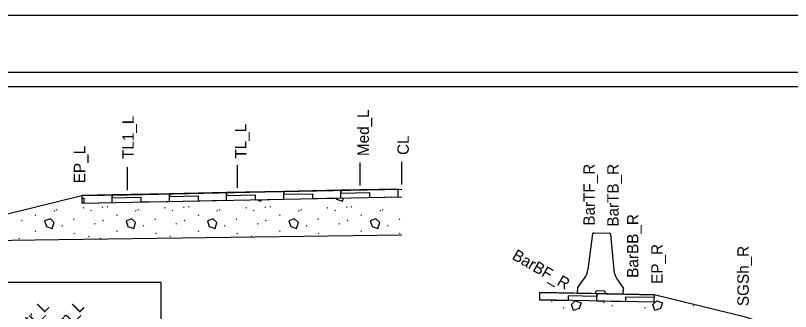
# Model space of a CAD drawing. Extents: x 0 to 1.42, y 0 to 0.92.
# Drawn here: x 0.309 to 0.874, y 0.701 to 0.917 of the extents above; entities that cross this region are included whole.
import ezdxf

# ---------------------------------------------------------------- set-up
doc = ezdxf.new("R2010")
doc.units = 0
for name, color, linetype in [('#plot_shape', 7, 'Continuous'), ('Level 14', 7, 'Continuous'), ('Level 63', 7, 'Continuous'), ('P_ODOT_PLAN_Border', 7, 'Continuous'), ('P_RDWY_PLAN_Detail', 7, 'Continuous'), ('P_RDWY_PLAN_DetailTx', 7, 'Continuous')]:
    doc.layers.add(name, color=color, linetype=linetype)

msp = doc.modelspace()

# ---------------------------------------------------------------- linework, layer by layer
at = {"layer": '#plot_shape'}
for points in [[(0, 0), (1.416666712, 0), (1.416666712, 0.916666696), (0, 0.916666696)], [(1.9999941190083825e-09, 1.3333161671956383e-09), (1.416666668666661, 1.3333161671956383e-09), (1.416666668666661, 0.916666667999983), (1.9999941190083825e-09, 0.916666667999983)]]:
    msp.add_lwpolyline(points, close=True, dxfattribs=at)
at = {"layer": 'Level 14'}
for p, q in [((0.7300565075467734, 0.7573254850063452), (0.7266381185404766, 0.7313387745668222)), ((0.730942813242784, 0.7581609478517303), (0.7423305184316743, 0.757933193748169)), ((0.7431772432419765, 0.7570630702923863), (0.7455538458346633, 0.7309604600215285)), ((0.7191560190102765, 0.7181983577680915), (0.7241561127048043, 0.7250988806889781)), ((0.7477898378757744, 0.7246262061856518), (0.7525045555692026, 0.7175313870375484)), ((0.7190740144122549, 0.71409812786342), (0.7191560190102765, 0.7181983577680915)), ((0.7524225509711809, 0.7134311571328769), (0.7525045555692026, 0.7175313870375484)), ((0.7190740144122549, 0.71409812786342), (0.7319214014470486, 0.7138411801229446)), ((0.7319214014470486, 0.7138411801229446), (0.7327851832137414, 0.7160115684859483)), ((0.7327851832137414, 0.7160115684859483), (0.7387988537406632, 0.7158912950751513)), ((0.7395751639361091, 0.7136881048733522), (0.7387988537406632, 0.7158912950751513)), ((0.7395751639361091, 0.7136881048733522), (0.7524225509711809, 0.7134311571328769))]:
    msp.add_line(p, q, dxfattribs=at)
for centre, start, end in [((0.7130856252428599, 0.7331225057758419), 324.0626538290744, 352.5107954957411), ((0.759168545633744, 0.7321988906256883), 185.20257327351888, 213.62627327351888)]:
    msp.add_arc(centre, 0.01367016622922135, start, end, dxfattribs=at)
for centre, major_axis, ratio, start_param, end_param in [((0.7308618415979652, 0.7572851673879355), (1.7651646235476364e-05, 0.0008825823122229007), 0.9122254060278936, 6.2052310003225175, 7.824384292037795), ((0.7423937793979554, 0.7570795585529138), (1.7194650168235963e-05, 0.000859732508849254), 0.9122254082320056, 4.71366656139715, 6.389459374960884)]:
    msp.add_ellipse(centre, major_axis=major_axis, ratio=ratio, start_param=start_param, end_param=end_param, dxfattribs=at)
at = {"layer": 'Level 63'}
for points in [[(0.9149281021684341, 0.24947988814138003), (0.07444556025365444, 0.24947988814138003), (0.07444556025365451, 0.8648110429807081), (0.9149281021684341, 0.8648110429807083)], [(0.41534290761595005, 0.6217266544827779), (0.2093492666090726, 0.6217266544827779), (0.2093492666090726, 0.7221789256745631), (0.41534290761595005, 0.7221789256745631)]]:
    msp.add_lwpolyline(points, close=True, dxfattribs=at)
at = {"layer": 'P_ODOT_PLAN_Border'}
for p, q in [((1.3087924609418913, 0.8750000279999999), (0.06250000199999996, 0.8750000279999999)), ((1.3087924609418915, 0.8750000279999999), (0.06250000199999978, 0.8750000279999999)), ((1.3087924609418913, 0.8750000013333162), (0.06250000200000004, 0.8750000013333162)), ((1.3087924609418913, 0.8750000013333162), (0.06250000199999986, 0.8750000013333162))]:
    msp.add_line(p, q, dxfattribs=at)
for points in [[(0.06250000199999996, 0.041666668), (1.395833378, 0.041666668), (1.395833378, 0.8750000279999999), (0.06250000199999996, 0.8750000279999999)], [(0.06250000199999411, 0.04166666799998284), (1.3958333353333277, 0.04166666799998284), (1.3958333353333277, 0.8750000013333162), (0.06250000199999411, 0.8750000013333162)]]:
    msp.add_lwpolyline(points, close=True, dxfattribs=at)
at = {"layer": 'P_RDWY_PLAN_Detail'}
for p, q in [((0.3558127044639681, 0.7848315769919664), (0.3558831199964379, 0.7847611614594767)), ((0.5838676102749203, 0.7843138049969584), (0.5835406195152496, 0.7839868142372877)), ((0.5836819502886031, 0.7843100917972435), (0.584005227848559, 0.7839868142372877)), ((0.3380731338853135, 0.7743840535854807), (0.33760852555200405, 0.7739194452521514)), ((0.33760852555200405, 0.7743840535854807), (0.3380731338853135, 0.7739194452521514)), ((0.3397766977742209, 0.7751592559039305), (0.3393120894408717, 0.774694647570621)), ((0.3393120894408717, 0.7751592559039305), (0.3397766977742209, 0.774694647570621)), ((0.35913476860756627, 0.7767079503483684), (0.3586707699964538, 0.776243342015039)), ((0.3586707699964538, 0.7767079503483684), (0.35913476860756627, 0.776243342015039)), ((0.36471006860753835, 0.7746937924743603), (0.364245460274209, 0.7742291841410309)), ((0.364245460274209, 0.7746937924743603), (0.36471006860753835, 0.7742291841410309)), ((0.37307301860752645, 0.7770176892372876), (0.37260841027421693, 0.7765530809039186)), ((0.37260841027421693, 0.7770176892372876), (0.37307301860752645, 0.7765530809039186)), ((0.3766354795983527, 0.7773274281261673), (0.37617087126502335, 0.7768628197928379)), ((0.37617087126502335, 0.7773274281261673), (0.3766354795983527, 0.7768628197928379)), ((0.3973879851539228, 0.7743840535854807), (0.3969233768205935, 0.7739194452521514)), ((0.3969233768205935, 0.7743840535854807), (0.3973879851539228, 0.7739194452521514)), ((0.39909154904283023, 0.7751592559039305), (0.39862694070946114, 0.774694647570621)), ((0.39862694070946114, 0.7751592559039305), (0.39909154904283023, 0.774694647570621)), ((0.41844961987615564, 0.7767079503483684), (0.41798562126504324, 0.776243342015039)), ((0.41798562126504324, 0.7767079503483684), (0.41844961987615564, 0.776243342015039)), ((0.42402491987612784, 0.7746937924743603), (0.42356031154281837, 0.7742291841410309)), ((0.42356031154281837, 0.7746937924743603), (0.42402491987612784, 0.7742291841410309)), ((0.43238786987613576, 0.7770176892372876), (0.43192326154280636, 0.7765530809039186)), ((0.43192326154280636, 0.7770176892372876), (0.43238786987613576, 0.7765530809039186)), ((0.43595033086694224, 0.7773274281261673), (0.43548572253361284, 0.7768628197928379)), ((0.43548572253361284, 0.7773274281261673), (0.43595033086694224, 0.7768628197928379)), ((0.45670283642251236, 0.7743840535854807), (0.45623822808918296, 0.7739194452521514)), ((0.45623822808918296, 0.7743840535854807), (0.45670283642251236, 0.7739194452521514)), ((0.45840640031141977, 0.7751592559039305), (0.4579417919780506, 0.774694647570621)), ((0.4579417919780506, 0.7751592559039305), (0.45840640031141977, 0.774694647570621)), ((0.47776447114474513, 0.7767079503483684), (0.4773004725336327, 0.776243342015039)), ((0.4773004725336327, 0.7767079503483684), (0.47776447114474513, 0.776243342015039)), ((0.4833397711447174, 0.7746937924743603), (0.4828751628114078, 0.7742291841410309)), ((0.4828751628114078, 0.7746937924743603), (0.4833397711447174, 0.7742291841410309)), ((0.4917027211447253, 0.7770176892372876), (0.4912381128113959, 0.7765530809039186)), ((0.4912381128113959, 0.7770176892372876), (0.4917027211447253, 0.7765530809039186)), ((0.4952651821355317, 0.7773274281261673), (0.4948005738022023, 0.7768628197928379)), ((0.4948005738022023, 0.7773274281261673), (0.4952651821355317, 0.7768628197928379)), ((0.5160176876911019, 0.7743840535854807), (0.5155530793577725, 0.7739194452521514)), ((0.5155530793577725, 0.7743840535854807), (0.5160176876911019, 0.7739194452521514)), ((0.5177212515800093, 0.7751592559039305), (0.5172566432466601, 0.774694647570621)), ((0.5172566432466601, 0.7751592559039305), (0.5177212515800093, 0.774694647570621)), ((0.5370793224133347, 0.7767079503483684), (0.5366153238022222, 0.776243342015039)), ((0.5366153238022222, 0.7767079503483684), (0.5370793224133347, 0.776243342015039)), ((0.5426546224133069, 0.7746937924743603), (0.5421900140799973, 0.7742291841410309)), ((0.5421900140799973, 0.7746937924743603), (0.5426546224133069, 0.7742291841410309)), ((0.5510175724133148, 0.7770176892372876), (0.5505529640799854, 0.7765530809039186)), ((0.5505529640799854, 0.7770176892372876), (0.5510175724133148, 0.7765530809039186)), ((0.5545800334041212, 0.7773274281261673), (0.5541154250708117, 0.7768628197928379)), ((0.5541154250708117, 0.7773274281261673), (0.5545800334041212, 0.7768628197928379)), ((0.5753325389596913, 0.7743840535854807), (0.574867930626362, 0.7739194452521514)), ((0.574867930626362, 0.7743840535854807), (0.5753325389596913, 0.7739194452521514)), ((0.5770361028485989, 0.7751592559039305), (0.5765714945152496, 0.774694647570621)), ((0.5765714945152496, 0.7751592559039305), (0.5770361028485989, 0.774694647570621)), ((0.3242897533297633, 0.7712866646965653), (0.3238251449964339, 0.7708220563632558)), ((0.3238251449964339, 0.7712866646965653), (0.3242897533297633, 0.7708220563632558)), ((0.3521662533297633, 0.7683441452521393), (0.3517016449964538, 0.7678795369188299)), ((0.3517016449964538, 0.7683441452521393), (0.3521662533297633, 0.7678795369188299)), ((0.3836046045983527, 0.7712866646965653), (0.3831399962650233, 0.7708220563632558)), ((0.3831399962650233, 0.7712866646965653), (0.3836046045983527, 0.7708220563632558)), ((0.41148110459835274, 0.7683441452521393), (0.4110164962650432, 0.7678795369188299)), ((0.4110164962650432, 0.7683441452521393), (0.41148110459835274, 0.7678795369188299)), ((0.4429194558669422, 0.7712866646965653), (0.4424548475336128, 0.7708220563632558)), ((0.4424548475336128, 0.7712866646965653), (0.4429194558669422, 0.7708220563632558)), ((0.47079595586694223, 0.7683441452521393), (0.47033134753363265, 0.7678795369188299)), ((0.47033134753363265, 0.7683441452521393), (0.47079595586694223, 0.7678795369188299)), ((0.5022343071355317, 0.7712866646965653), (0.5017696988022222, 0.7708220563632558)), ((0.5017696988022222, 0.7712866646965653), (0.5022343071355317, 0.7708220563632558)), ((0.5301108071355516, 0.7683441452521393), (0.5296461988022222, 0.7678795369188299)), ((0.5296461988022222, 0.7683441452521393), (0.5301108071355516, 0.7678795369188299)), ((0.5615491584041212, 0.7712866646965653), (0.5610845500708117, 0.7708220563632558)), ((0.5610845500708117, 0.7712866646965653), (0.5615491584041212, 0.7708220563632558)), ((0.5894256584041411, 0.7683441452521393), (0.5889610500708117, 0.7678795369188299)), ((0.5889610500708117, 0.7683441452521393), (0.5894256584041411, 0.7678795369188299)), ((0.31422323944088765, 0.7674149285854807), (0.31375863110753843, 0.7669503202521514)), ((0.31375863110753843, 0.7674149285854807), (0.31422323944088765, 0.7669503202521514)), ((0.34364843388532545, 0.7635431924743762), (0.34318382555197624, 0.763078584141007)), ((0.34318382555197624, 0.7635431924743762), (0.34364843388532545, 0.763078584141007)), ((0.36749771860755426, 0.7649370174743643), (0.36703311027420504, 0.7644724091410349)), ((0.36703311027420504, 0.7649370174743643), (0.36749771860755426, 0.7644724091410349)), ((0.3735380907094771, 0.7674149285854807), (0.37307348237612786, 0.7669503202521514)), ((0.37307348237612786, 0.7674149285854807), (0.3735380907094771, 0.7669503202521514)), ((0.4029632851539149, 0.7635431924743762), (0.40249867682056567, 0.763078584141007)), ((0.40249867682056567, 0.7635431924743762), (0.4029632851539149, 0.763078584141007)), ((0.42681256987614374, 0.7649370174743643), (0.4263479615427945, 0.7644724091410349)), ((0.4263479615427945, 0.7649370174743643), (0.42681256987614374, 0.7644724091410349)), ((0.43285294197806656, 0.7674149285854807), (0.4323883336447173, 0.7669503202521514)), ((0.4323883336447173, 0.7674149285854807), (0.43285294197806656, 0.7669503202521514)), ((0.4622781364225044, 0.7635431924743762), (0.4618135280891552, 0.763078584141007)), ((0.4618135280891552, 0.7635431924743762), (0.4622781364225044, 0.763078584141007)), ((0.48612742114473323, 0.7649370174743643), (0.485662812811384, 0.7644724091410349)), ((0.485662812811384, 0.7649370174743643), (0.48612742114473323, 0.7644724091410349)), ((0.49216779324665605, 0.7674149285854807), (0.49170318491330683, 0.7669503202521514)), ((0.49170318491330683, 0.7674149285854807), (0.49216779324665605, 0.7669503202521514)), ((0.5215929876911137, 0.7635431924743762), (0.5211283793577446, 0.763078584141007)), ((0.5211283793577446, 0.7635431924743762), (0.5215929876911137, 0.763078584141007)), ((0.5454422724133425, 0.7649370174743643), (0.5449776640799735, 0.7644724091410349)), ((0.5449776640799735, 0.7649370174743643), (0.5454422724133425, 0.7644724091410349)), ((0.5514826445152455, 0.7674149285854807), (0.5510180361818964, 0.7669503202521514)), ((0.5510180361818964, 0.7674149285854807), (0.5514826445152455, 0.7669503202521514)), ((0.5809078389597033, 0.7635431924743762), (0.5804432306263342, 0.763078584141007)), ((0.5804432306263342, 0.7635431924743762), (0.5809078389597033, 0.763078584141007)), ((0.3242897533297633, 0.7596714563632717), (0.3238251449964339, 0.7592068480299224)), ((0.3238251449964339, 0.7596714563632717), (0.3242897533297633, 0.7592068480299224)), ((0.3524759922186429, 0.7579678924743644), (0.35201138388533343, 0.757503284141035)), ((0.35201138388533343, 0.7579678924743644), (0.3524759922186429, 0.757503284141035)), ((0.3836046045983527, 0.7596714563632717), (0.3831399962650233, 0.7592068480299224)), ((0.3831399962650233, 0.7596714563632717), (0.3836046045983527, 0.7592068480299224)), ((0.41179084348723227, 0.7579678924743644), (0.4113262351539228, 0.757503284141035)), ((0.4113262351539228, 0.7579678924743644), (0.41179084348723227, 0.757503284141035)), ((0.4429194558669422, 0.7596714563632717), (0.4424548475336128, 0.7592068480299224)), ((0.4424548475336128, 0.7596714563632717), (0.4429194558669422, 0.7592068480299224)), ((0.4711056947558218, 0.7579678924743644), (0.47064108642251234, 0.757503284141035)), ((0.47064108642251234, 0.7579678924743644), (0.4711056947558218, 0.757503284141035)), ((0.5022343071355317, 0.7596714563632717), (0.5017696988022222, 0.7592068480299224)), ((0.5017696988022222, 0.7596714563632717), (0.5022343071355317, 0.7592068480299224)), ((0.5304205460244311, 0.7579678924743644), (0.5299559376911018, 0.757503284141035)), ((0.5299559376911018, 0.7579678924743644), (0.5304205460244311, 0.757503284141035)), ((0.5615491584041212, 0.7596714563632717), (0.5610845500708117, 0.7592068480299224)), ((0.5610845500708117, 0.7596714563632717), (0.5615491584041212, 0.7592068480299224)), ((0.5897353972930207, 0.7579678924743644), (0.5892707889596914, 0.757503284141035)), ((0.5892707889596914, 0.7579678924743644), (0.5897353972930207, 0.757503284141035)), ((0.312209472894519, 0.7542510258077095), (0.31174486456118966, 0.7537864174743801)), ((0.31174486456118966, 0.7542510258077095), (0.312209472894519, 0.7537864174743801)), ((0.36300650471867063, 0.7557997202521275), (0.36254189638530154, 0.755335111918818)), ((0.36254189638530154, 0.7557997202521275), (0.36300650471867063, 0.755335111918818)), ((0.37152432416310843, 0.7542510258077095), (0.3710597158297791, 0.7537864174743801)), ((0.3710597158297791, 0.7542510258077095), (0.37152432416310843, 0.7537864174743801)), ((0.4223213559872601, 0.7557997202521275), (0.4218567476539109, 0.755335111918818)), ((0.4218567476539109, 0.7557997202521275), (0.4223213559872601, 0.755335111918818)), ((0.4816362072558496, 0.7557997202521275), (0.4811715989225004, 0.755335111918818)), ((0.4811715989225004, 0.7557997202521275), (0.4816362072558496, 0.755335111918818)), ((0.7000815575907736, 0.7085692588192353), (0.700546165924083, 0.7081046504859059)), ((0.700546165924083, 0.7085692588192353), (0.7000815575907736, 0.7081046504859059)), ((0.7380245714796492, 0.7076400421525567), (0.7384891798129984, 0.7071754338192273)), ((0.7384891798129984, 0.7076400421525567), (0.7380245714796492, 0.7071754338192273)), ((0.7975714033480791, 0.707407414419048), (0.7973394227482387, 0.7071754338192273)), ((0.7975722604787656, 0.7074072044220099), (0.7978040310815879, 0.7071754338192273)), ((0.7085993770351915, 0.7037683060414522), (0.7090639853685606, 0.703303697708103)), ((0.7090639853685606, 0.7037683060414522), (0.7085993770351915, 0.703303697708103)), ((0.744064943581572, 0.7051621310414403), (0.7445295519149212, 0.7046975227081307)), ((0.7445295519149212, 0.7051621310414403), (0.744064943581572, 0.7046975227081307)), ((0.7679142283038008, 0.7037683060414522), (0.76837883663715, 0.703303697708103)), ((0.76837883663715, 0.7037683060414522), (0.7679142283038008, 0.703303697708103)), ((0.8033797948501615, 0.7051621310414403), (0.8038444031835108, 0.7046975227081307)), ((0.8038444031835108, 0.7051621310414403), (0.8033797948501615, 0.7046975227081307))]:
    msp.add_line(p, q, dxfattribs=at)
for points in [[(0.13057917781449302, 0.7575004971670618), (0.187180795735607, 0.7433500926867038), (0.2205141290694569, 0.7516834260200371), (0.3576843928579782, 0.7852901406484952), (0.3910177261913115, 0.7859568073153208), (0.49101772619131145, 0.7879568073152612), (0.5910177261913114, 0.7899568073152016)], [(0.3576843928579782, 0.7852901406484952), (0.3577943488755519, 0.7797923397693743), (0.5910177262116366, 0.7844568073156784)], [(0.4289329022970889, 0.781215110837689), (0.4289807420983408, 0.7811991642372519), (0.4289864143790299, 0.7812161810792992)], [(0.48489030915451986, 0.782334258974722), (0.4882955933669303, 0.7811991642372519), (0.4886993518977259, 0.782410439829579)], [(0.5431269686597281, 0.783498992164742), (0.5434289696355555, 0.7825929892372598), (0.5476104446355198, 0.7811991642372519), (0.548412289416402, 0.7836046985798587)], [(0.22051412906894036, 0.7516834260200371), (0.34101772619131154, 0.7532901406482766), (0.5910177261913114, 0.7566234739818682)], [(0.8810170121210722, 0.6834707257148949), (0.8414791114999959, 0.6966500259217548), (0.7748124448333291, 0.712983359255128), (0.7414791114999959, 0.7136500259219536), (0.6914791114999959, 0.714650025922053)], [(0.7748124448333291, 0.712983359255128), (0.7747024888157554, 0.7074855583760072), (0.6914791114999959, 0.7091500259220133)], [(0.7174696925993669, 0.7085550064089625), (0.7216084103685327, 0.7071754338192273), (0.7202145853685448, 0.7029939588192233), (0.7160331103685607, 0.7016001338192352), (0.7146392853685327, 0.7057816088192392), (0.7174137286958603, 0.7085560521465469)]]:
    msp.add_lwpolyline(points, dxfattribs=at)
for points in [[(0.3799498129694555, 0.7858448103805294), (0.3576843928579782, 0.7852901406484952), (0.3577238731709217, 0.7833161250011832), (0.3591164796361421, 0.7833439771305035), (0.3591164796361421, 0.7798187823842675), (0.3799498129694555, 0.7802354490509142)], [(0.42161647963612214, 0.7866781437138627), (0.3799498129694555, 0.7858448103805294), (0.3799498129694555, 0.7837606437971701), (0.4007831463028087, 0.7841773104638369), (0.4007831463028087, 0.7806521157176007), (0.42161647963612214, 0.7810687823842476)], [(0.46328314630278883, 0.7875114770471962), (0.42161647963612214, 0.7866781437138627), (0.42161647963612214, 0.7845939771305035), (0.4424498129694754, 0.7850106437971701), (0.4424498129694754, 0.7814854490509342), (0.46328314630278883, 0.781902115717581)], [(0.5049498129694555, 0.7883448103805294), (0.46328314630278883, 0.7875114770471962), (0.46328314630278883, 0.7854273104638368), (0.48411647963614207, 0.7858439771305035), (0.48411647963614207, 0.7823187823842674), (0.5049498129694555, 0.7827354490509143)], [(0.5466164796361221, 0.7891781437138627), (0.5049498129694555, 0.7883448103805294), (0.5049498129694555, 0.7862606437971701), (0.5257831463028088, 0.7866773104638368), (0.5257831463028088, 0.7831521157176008), (0.5466164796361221, 0.7835687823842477)], [(0.5882831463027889, 0.7900114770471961), (0.5466164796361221, 0.7891781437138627), (0.5466164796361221, 0.7870939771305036), (0.5674498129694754, 0.7875106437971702), (0.5674498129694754, 0.7839854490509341), (0.5882831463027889, 0.7844021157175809)], [(0.3362147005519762, 0.7613750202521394), (0.33760852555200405, 0.7655564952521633), (0.33482087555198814, 0.7683441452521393), (0.330639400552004, 0.7669503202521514), (0.3320332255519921, 0.7627688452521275)], [(0.39552955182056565, 0.7613750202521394), (0.3969233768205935, 0.7655564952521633), (0.39413572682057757, 0.7683441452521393), (0.38995425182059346, 0.7669503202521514), (0.39134807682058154, 0.7627688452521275)], [(0.45484440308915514, 0.7613750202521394), (0.45623822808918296, 0.7655564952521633), (0.4534505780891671, 0.7683441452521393), (0.449269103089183, 0.7669503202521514), (0.4506629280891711, 0.7627688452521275)], [(0.5141592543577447, 0.7613750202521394), (0.5155530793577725, 0.7655564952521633), (0.5127654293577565, 0.7683441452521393), (0.5085839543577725, 0.7669503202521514), (0.5099777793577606, 0.7627688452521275)], [(0.5734741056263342, 0.7613750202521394), (0.574867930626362, 0.7655564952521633), (0.5720802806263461, 0.7683441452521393), (0.567898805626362, 0.7669503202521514), (0.5692926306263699, 0.7627688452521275)], [(0.6914791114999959, 0.7146500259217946), (0.7331457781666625, 0.7138166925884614), (0.7331457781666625, 0.7117325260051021), (0.7123124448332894, 0.7121491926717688), (0.7123124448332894, 0.7086239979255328), (0.6914791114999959, 0.7090406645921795)], [(0.7331457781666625, 0.7138166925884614), (0.7748124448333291, 0.712983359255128), (0.7748124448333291, 0.7108991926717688), (0.7539791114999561, 0.7113158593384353), (0.7539791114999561, 0.7077906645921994), (0.7331457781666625, 0.7082073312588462)], [(0.7753479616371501, 0.7016001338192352), (0.7739541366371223, 0.7057816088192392), (0.7767417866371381, 0.7085692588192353), (0.7809232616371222, 0.7071754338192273), (0.7795294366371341, 0.7029939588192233)]]:
    msp.add_lwpolyline(points, close=True, dxfattribs=at)
at = {"layer": 'P_RDWY_PLAN_DetailTx'}
for p, q in [((0.5605075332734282, 0.7926799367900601), (0.5605075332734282, 0.8093466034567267)), ((0.5910177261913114, 0.793290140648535), (0.5910177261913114, 0.8099568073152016)), ((0.3910177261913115, 0.7892901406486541), (0.3910177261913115, 0.8059568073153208)), ((0.4711910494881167, 0.7908936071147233), (0.4711910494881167, 0.8075602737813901))]:
    msp.add_line(p, q, dxfattribs=at)

# ---------------------------------------------------------------- texts
for s, height, rotation, p in [('Med_L', 0.008330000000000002, 90.00000153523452, (0.5669841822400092, 0.8141318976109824)), ('TL1_L', 0.008330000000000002, 90.00000153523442, (0.3956222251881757, 0.8120038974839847)), ('TL_L', 0.008330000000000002, 90.0000015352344, (0.4776676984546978, 0.812345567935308)), ('CL', 0.008330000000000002, 90.00000153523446, (0.59604460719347, 0.8149567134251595)), ('EP_L', 0.008330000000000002, 90.00000153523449, (0.3601884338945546, 0.7942870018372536)), ('BarTF_R', 0.008330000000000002, 89.99999846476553, (0.7316537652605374, 0.7633758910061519)), ('BarTB_R', 0.008330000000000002, 89.99999846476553, (0.7490015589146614, 0.7626376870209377)), ('BarBB_R', 0.008330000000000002, 89.99999846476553, (0.7633965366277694, 0.7253583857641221)), ('BarBF_R', 0.00833, 329.99999437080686, (0.67069319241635, 0.7393783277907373)), ('EP_R', 0.008330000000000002, 89.99999846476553, (0.7811134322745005, 0.720929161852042)), ('SGSh_R', 0.008330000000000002, 89.99999846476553, (0.843860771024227, 0.7046886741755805)), ('Gtr_L', 0.008330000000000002, 44.99999923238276, (0.31474654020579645, 0.6841041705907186)), ('Pan_L', 0.008330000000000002, 44.99999923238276, (0.3372595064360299, 0.6809509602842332))]:
    msp.add_text(s, height=height, rotation=rotation, dxfattribs=at).set_placement(p)

doc.saveas('drawing.dxf')
